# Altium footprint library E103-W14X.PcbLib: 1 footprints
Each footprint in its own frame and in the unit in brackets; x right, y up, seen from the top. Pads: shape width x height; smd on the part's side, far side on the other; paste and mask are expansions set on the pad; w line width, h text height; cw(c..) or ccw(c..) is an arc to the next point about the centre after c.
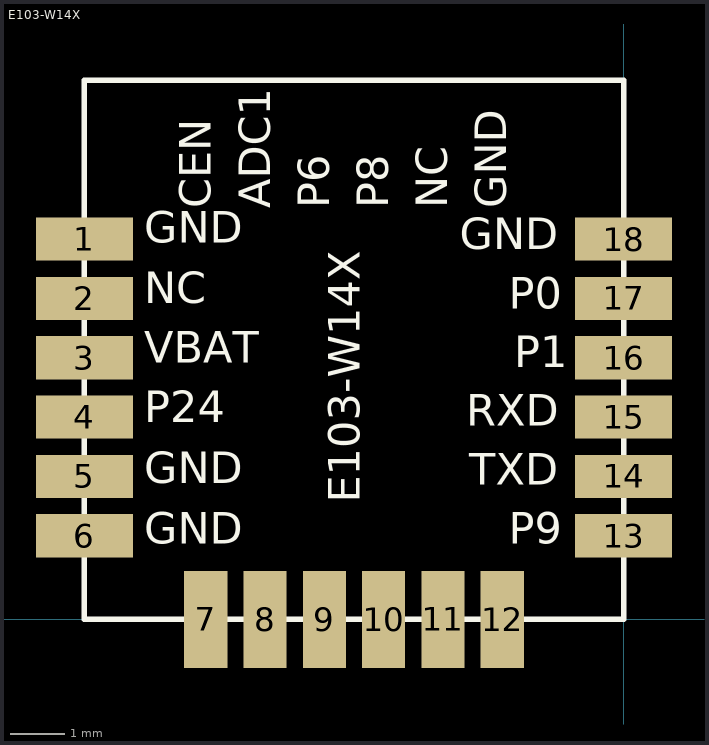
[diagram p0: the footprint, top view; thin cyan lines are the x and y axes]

## E103-W14X [mm]
pads (18):
  rect 1.8x0.8 smd: 1(-10,7.05) 2(-10,5.95) 3(-10,4.85) 4(-10,3.75) 5(-10,2.65) 6(-10,1.55) 13(0,1.55) 14(0,2.65) 15(0,3.75) 16(0,4.85) 17(0,5.95) 18(0,7.05)
  rect 0.8x1.8 smd: 7(-7.75,0) 8(-6.65,0) 9(-5.55,0) 10(-4.45,0) 11(-3.35,0) 12(-2.25,0)
Top Overlay:
  lines w0.1: -10,0 0,0 0,10 -10,10 -10,0
  text "P8" at -4.171,7.628 h1
  text "P6" at -5.267,7.628 h1
  text "NC" at -3.076,7.628 h1
  text "CEN" at -7.458,7.628 h1
  text "GND" at -1.98,7.628 h1
  text "ADC1" at -6.362,7.628 h1
  text "P9" at -2.13,1.205 h1
  text "GND" at -8.89,6.793 h1
  text "E103-W14X" at -4.699,2.159 h1
  text "P1" at -2.026,4.478 h1
  text "GND" at -8.89,2.331 h1
  text "P24" at -8.89,3.457 h1
  text "VBAT" at -8.89,4.563 h1
  text "TXD" at -2.866,2.305 h1
  text "RXD" at -2.921,3.391 h1
  text "P0" at -2.127,5.566 h1
  text "GND" at -3.042,6.666 h1
  text "GND" at -8.89,1.205 h1
  text "NC" at -8.89,5.667 h1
